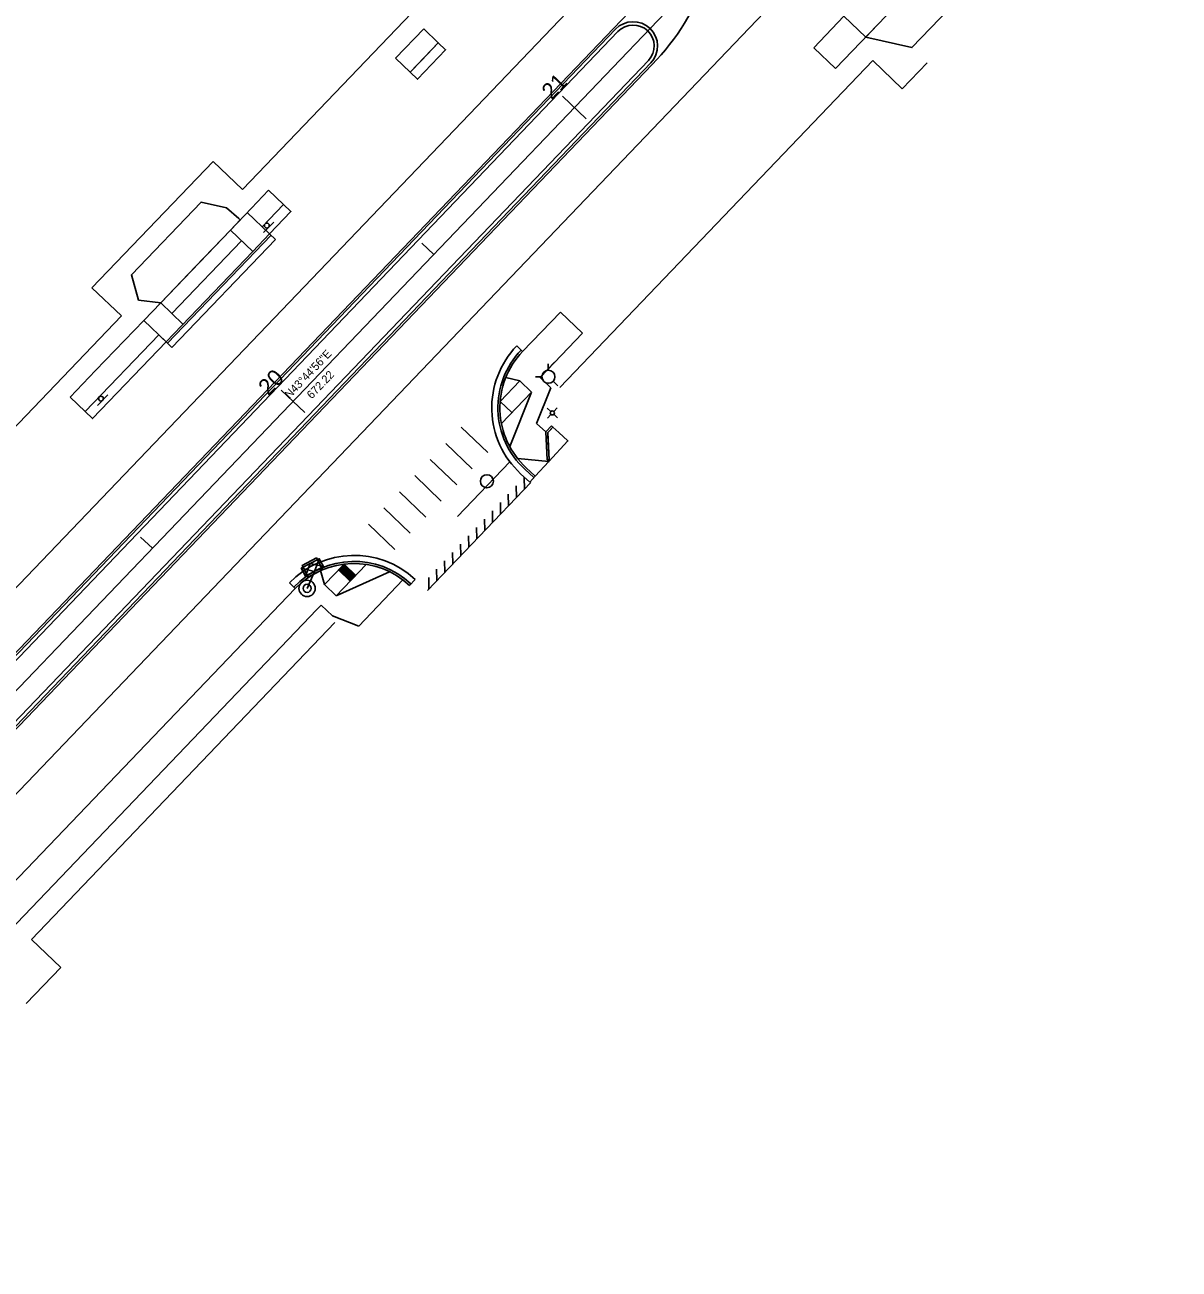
# Model space of a CAD drawing. Extents: x 2377903 to 2496516, y 664638 to 732785.
# Drawn here: x 2378536.6 to 2378820.2, y 730603.2 to 730909 of the extents above; entities that cross this region are included whole.
import ezdxf

# ---------------------------------------------------------------- set-up
doc = ezdxf.new("R2010")
doc.units = 0
for name, color, linetype in [('ALG_CL_BLUE_Horiz', 7, 'Continuous'), ('ALG_CL_BLUE_Horiz-Stationing', 7, 'Continuous'), ('ALG_CL_BLUE_Horiz-Text', 7, 'Continuous'), ('Default', 7, 'Continuous'), ('DES_ROADWAY_Approach', 7, 'Continuous'), ('DES_ROADWAY_Concrete-Pavement', 7, 'Continuous'), ('DES_ROADWAY_Curb-Back', 7, 'Continuous'), ('DES_ROADWAY_Curb-Face-LINE STYLE', 7, 'Continuous'), ('DES_ROADWAY_Edge-of-Pavement', 7, 'Continuous'), ('DES_ROADWAY_Misc-SAW CUT', 7, 'Continuous'), ('DES_ROADWAY_Sidewalk', 7, 'Continuous'), ('DES_ROADWAY_T-DOMES', 7, 'Continuous'), ('ENV_EROSN_Temp-Erosn-Ctrl-Details', 7, 'Continuous'), ('HYDR_Inlets', 7, 'Continuous'), ('ROW_P_PUA', 7, 'Continuous'), ('TOPO_WTRUTIL_Fire-Hydrant', 7, 'Continuous'), ('TOPO_WTRUTIL_Valve', 7, 'Continuous'), ('TRAF_PAVEMARK_Stop-Bar', 7, 'Continuous'), ('TRAF_PAVEMARK_White_SKIP 12-38', 7, 'Continuous'), ('TRAF_PAVEMARK_Yellow', 7, 'Continuous'), ('TRAF_SIGN_Post', 7, 'Continuous'), ('UTIL_STORM_Manhole', 7, 'Continuous'), ('UTIL_STORM_Pipe', 7, 'Continuous')]:
    doc.layers.add(name, color=color, linetype=linetype)

# ---------------------------------------------------------------- blocks, each defined once
blk = doc.blocks.new('MH_7')
at = {"layer": 'Default'}
for radius in [0.0254, 0.0127]:
    blk.add_circle((0, 0), radius, dxfattribs=at)
blk = doc.blocks.new('STSIGN_4')
at = {"layer": 'Default'}
for p, q in [((-0.0223, 0), (-0.0064, 0)), ((0, 0.0223), (0, 0.0064)), ((0.0064, 0), (0.0223, 0)), ((0, -0.0064), (0, -0.0223))]:
    blk.add_line(p, q, dxfattribs=at)
blk.add_circle((0, 0), 0.00635, dxfattribs=at)

msp = doc.modelspace()

# ---------------------------------------------------------------- linework, layer by layer
at = {"layer": 'ALG_CL_BLUE_Horiz'}
msp.add_line((2378375.43, 730579.33), (2378840.27, 731064.93), dxfattribs=at)
at = {"layer": 'ALG_CL_BLUE_Horiz-Stationing'}
for p, q in [((2378668.72, 730891.5), (2378674.5, 730885.97)), ((2378634.15, 730855.39), (2378637.04, 730852.62)), ((2378599.57, 730819.27), (2378605.35, 730813.73)), ((2378565, 730783.15), (2378567.89, 730780.38))]:
    msp.add_line(p, q, dxfattribs=at)
at = {"layer": 'Default'}
msp.add_line((2378572.68, 730838.08), (2378589.81, 730855.95), dxfattribs=at)
at = {"layer": 'DES_ROADWAY_Approach'}
for points in [[(2378762.97, 730926.67), (2378766.04, 730915.42), (2378754.57, 730903.46), (2378743.2, 730906.04), (2378746.11, 730909.08)], [(2378631.25, 730897.4), (2378638.16, 730904.63), (2378639.96, 730902.9), (2378633.05, 730895.67)], [(2378564.44, 730841.34), (2378562.74, 730847.59), (2378579.85, 730865.49), (2378586.11, 730864.08), (2378586.11, 730864.07), (2378589.12, 730861.46), (2378589.49, 730861.11), (2378587.08, 730858.58), (2378578.52, 730849.63), (2378569.96, 730840.68)], [(2378594.9, 730859.39), (2378600.14, 730864.88), (2378601.94, 730863.16), (2378596.7, 730857.66)], [(2378551.35, 730814), (2378569.44, 730832.87), (2378570.24, 730832.1), (2378571.24, 730831.14), (2378553.16, 730812.27)], [(2378665.38, 730802.12), (2378665.11, 730807.99), (2378665.1, 730808.29), (2378665.09, 730808.6), (2378665.08, 730808.82), (2378665.43, 730809.2), (2378665.49, 730809.27), (2378665.64, 730809.43), (2378666.31, 730810.17), (2378667.78, 730808.82), (2378670.02, 730806.78), (2378665.35, 730801.67)]]:
    msp.add_lwpolyline(points, close=True, dxfattribs=at)
at = {"layer": 'DES_ROADWAY_Concrete-Pavement'}
for p, q in [((2378524.37, 730742.39), (2378682.32, 730907.39)), ((2378689.78, 730900.25), (2378531.83, 730735.24))]:
    msp.add_line(p, q, dxfattribs=at)
msp.add_arc((2378686.05, 730903.82), 5.17, 316.2512, 136.2512, dxfattribs=at)
at = {"layer": 'DES_ROADWAY_Curb-Back'}
for p, q in [((2378524.37, 730742.39), (2378682.32, 730907.39)), ((2378531.83, 730735.24), (2378689.78, 730900.25)), ((2378661.99, 730798.11), (2378659.75, 730800.17))]:
    msp.add_line(p, q, dxfattribs=at)
msp.add_lwpolyline([(2378571.24, 730831.14), (2378592.54, 730853.33), (2378596.7, 730857.66)], dxfattribs=at)
for centre, radius, start, end in [((2378686.05, 730903.82), 5.17, 316.2512, 136.2512), ((2378673.3, 730814.89), 20, 136.1887, 227.3533), ((2378617.45, 730756.64), 20, 46.9312, 136.2336)]:
    msp.add_arc(centre, radius, start, end, dxfattribs=at)
at = {"layer": 'DES_ROADWAY_Curb-Face-LINE STYLE'}
for p, q in [((2378571.6, 730830.79), (2378597.06, 730857.31)), ((2378659.41, 730799.81), (2378661.65, 730797.75))]:
    msp.add_line(p, q, dxfattribs=at)
for centre, start, end in [((2378673.3, 730814.89), 136.1887, 227.3533), ((2378617.45, 730756.64), 46.9312, 136.2336)]:
    msp.add_arc(centre, 20.5, start, end, dxfattribs=at)
at = {"layer": 'DES_ROADWAY_Edge-of-Pavement'}
for p, q in [((2378523.76, 730742.96), (2378681.72, 730907.97)), ((2378532.43, 730734.67), (2378690.38, 730899.67)), ((2378596.7, 730857.66), (2378598.14, 730856.27)), ((2378572.68, 730829.76), (2378598.14, 730856.27)), ((2378571.24, 730831.14), (2378572.68, 730829.76)), ((2378658.87, 730828.73), (2378657.43, 730830.12)), ((2378658.4, 730798.7), (2378660.64, 730796.64)), ((2378635.5, 730770.03), (2378660.88, 730796.54)), ((2378661.99, 730798.11), (2378660.64, 730796.64)), ((2378601.56, 730771.86), (2378603, 730770.48)), ((2378631.1, 730771.25), (2378632.47, 730772.71))]:
    msp.add_line(p, q, dxfattribs=at)
for centre, radius, start, end in [((2378686.05, 730903.82), 6, 316.2512, 136.2512), ((2378673.3, 730814.89), 22, 136.1887, 227.3533), ((2378617.45, 730756.64), 22, 46.9312, 136.2336)]:
    msp.add_arc(centre, radius, start, end, dxfattribs=at)
at = {"layer": 'DES_ROADWAY_Misc-SAW CUT'}
for p, q in [((2378657.39, 730792.89), (2378657.33, 730795.72)), ((2378659.34, 730794.94), (2378659.28, 730797.77)), ((2378655.43, 730790.85), (2378655.37, 730793.68)), ((2378651.51, 730786.76), (2378651.45, 730789.59)), ((2378653.47, 730788.8), (2378653.41, 730791.63)), ((2378649.56, 730784.71), (2378649.5, 730787.54)), ((2378645.64, 730780.62), (2378645.58, 730783.45)), ((2378647.6, 730782.67), (2378647.54, 730785.5)), ((2378643.68, 730778.58), (2378643.62, 730781.41)), ((2378639.77, 730774.49), (2378639.71, 730777.32)), ((2378641.73, 730776.53), (2378641.67, 730779.36)), ((2378637.81, 730772.44), (2378637.75, 730775.27)), ((2378635.85, 730770.4), (2378635.8, 730773.23))]:
    msp.add_line(p, q, dxfattribs=at)
at = {"layer": 'DES_ROADWAY_Sidewalk'}
for p, q in [((2378737.85, 730911.18), (2378730.44, 730903.42)), ((2378735.79, 730898.31), (2378746.11, 730909.08)), ((2378743.2, 730906.04), (2378737.85, 730911.18)), ((2378634.6, 730908.03), (2378627.66, 730900.83)), ((2378638.16, 730904.63), (2378634.6, 730908.03)), ((2378634, 730900.28), (2378638.16, 730904.63)), ((2378735.79, 730898.31), (2378730.44, 730903.42)), ((2378631.25, 730897.4), (2378627.66, 730900.83)), ((2378631.25, 730897.4), (2378634, 730900.28)), ((2378596.45, 730868.41), (2378592.25, 730864)), ((2378600.14, 730864.88), (2378596.45, 730868.41)), ((2378592.25, 730864), (2378587.08, 730858.58)), ((2378591.22, 730862.92), (2378596.7, 730857.66)), ((2378594.9, 730859.39), (2378600.14, 730864.88)), ((2378587.08, 730858.58), (2378569.96, 730840.68)), ((2378587.08, 730858.58), (2378592.54, 730853.33)), ((2378569.96, 730840.68), (2378565.79, 730836.37)), ((2378569.96, 730840.68), (2378575.39, 730835.47)), ((2378668.18, 730838.44), (2378658.87, 730828.73)), ((2378673.58, 730833.26), (2378668.18, 730838.44)), ((2378553.89, 730824.05), (2378565.79, 730836.37)), ((2378565.79, 730836.37), (2378571.24, 730831.14)), ((2378569.44, 730832.87), (2378551.35, 730814)), ((2378663.16, 730822.34), (2378673.58, 730833.26)), ((2378663.3, 730822.49), (2378666.75, 730826.11)), ((2378547.65, 730817.55), (2378553.89, 730824.05)), ((2378653.37, 730816.49), (2378658.21, 730821.54)), ((2378654.74, 730822.33), (2378658.21, 730821.54)), ((2378661.1, 730818.78), (2378658.21, 730821.54)), ((2378665.82, 730819.79), (2378662.31, 730811.09)), ((2378665.82, 730819.79), (2378663.16, 730822.34)), ((2378551.35, 730814), (2378547.65, 730817.55)), ((2378653.68, 730811.04), (2378661.1, 730818.78)), ((2378661.1, 730818.78), (2378655.7, 730805.39)), ((2378656.25, 730813.72), (2378653.37, 730816.49)), ((2378662.31, 730811.09), (2378664.57, 730809.01)), ((2378664.57, 730809.01), (2378665.94, 730810.51)), ((2378664.88, 730802.1), (2378664.57, 730809.01)), ((2378665.08, 730808.82), (2378666.31, 730810.17)), ((2378665.38, 730802.12), (2378665.08, 730808.82)), ((2378666.31, 730810.17), (2378665.94, 730810.51)), ((2378657.67, 730802.41), (2378665.35, 730801.67)), ((2378665.35, 730801.67), (2378661.99, 730798.11)), ((2378664.88, 730802.1), (2378665.38, 730802.12)), ((2378664.88, 730802.1), (2378665.35, 730801.67)), ((2378610.16, 730771.44), (2378609.23, 730774.88)), ((2378610.16, 730771.44), (2378615.01, 730776.49)), ((2378613.05, 730768.67), (2378620.47, 730776.41)), ((2378613.05, 730768.67), (2378626.2, 730774.62)), ((2378617.89, 730773.72), (2378615.01, 730776.49)), ((2378613.05, 730768.67), (2378610.16, 730771.44)), ((2378629.43, 730772.65), (2378618.64, 730761.23)), ((2378527.48, 730691.63), (2378603, 730770.48)), ((2378609.4, 730766.39), (2378608.17, 730765.16)), ((2378612.12, 730763.79), (2378609.4, 730766.39)), ((2378612.12, 730763.79), (2378618.64, 730761.23))]:
    msp.add_line(p, q, dxfattribs=at)
msp.add_lwpolyline([(2378532.77, 730686.32), (2378606.65, 730763.63), (2378608.17, 730765.16)], dxfattribs=at)
at = {"layer": 'DES_ROADWAY_T-DOMES'}
for p, q in [((2378613.62, 730775.05), (2378616.51, 730772.28)), ((2378615.01, 730776.49), (2378617.89, 730773.72))]:
    msp.add_line(p, q, dxfattribs=at)
msp.add_lwpolyline([(2378616.51, 730772.28), (2378613.62, 730775.05), (2378615.01, 730776.49), (2378617.89, 730773.72)], close=True, dxfattribs=at)
for centre in [(2378613.92, 730775.07), (2378614.05, 730775.21), (2378614.06, 730774.93), (2378614.19, 730775.35), (2378614.2, 730775.07), (2378614.2, 730774.79), (2378614.33, 730775.5), (2378614.34, 730775.22), (2378614.34, 730774.93), (2378614.35, 730774.65), (2378614.47, 730775.64), (2378614.48, 730775.36), (2378614.48, 730775.08), (2378614.49, 730774.79), (2378614.49, 730774.51), (2378614.61, 730775.79), (2378614.61, 730775.5), (2378614.62, 730775.22), (2378614.63, 730774.94), (2378614.63, 730774.66), (2378614.64, 730774.37), (2378614.75, 730775.93), (2378614.75, 730775.65), (2378614.76, 730775.37), (2378614.76, 730775.08), (2378614.77, 730774.8), (2378614.78, 730774.52), (2378614.78, 730774.23), (2378614.89, 730776.08), (2378614.89, 730775.79), (2378614.9, 730775.51), (2378614.9, 730775.23), (2378614.91, 730774.94), (2378614.91, 730774.66), (2378614.92, 730774.38), (2378614.93, 730774.1), (2378615.02, 730776.22), (2378615.03, 730775.94), (2378615.04, 730775.65), (2378615.04, 730775.37), (2378615.05, 730775.09), (2378615.05, 730774.81), (2378615.06, 730774.52), (2378615.06, 730774.24), (2378615.07, 730773.96), (2378615.17, 730776.08), (2378615.17, 730775.8), (2378615.18, 730775.52), (2378615.19, 730775.23), (2378615.19, 730774.95), (2378615.2, 730774.67), (2378615.2, 730774.38), (2378615.21, 730774.1), (2378615.31, 730775.94), (2378615.32, 730775.66), (2378615.32, 730775.38), (2378615.33, 730775.09), (2378615.34, 730774.81), (2378615.34, 730774.53), (2378615.35, 730774.25), (2378615.35, 730773.96), (2378615.46, 730775.8), (2378615.46, 730775.52), (2378615.47, 730775.24), (2378615.47, 730774.96), (2378615.48, 730774.67), (2378615.49, 730774.39), (2378615.49, 730774.11), (2378615.6, 730775.67), (2378615.61, 730775.38), (2378615.61, 730775.1), (2378615.62, 730774.82), (2378615.62, 730774.53), (2378615.63, 730774.25), (2378615.64, 730773.97), (2378615.75, 730775.53), (2378615.75, 730775.24), (2378615.76, 730774.96), (2378615.76, 730774.68), (2378615.77, 730774.4), (2378615.77, 730774.11), (2378615.89, 730775.39), (2378615.9, 730775.11), (2378615.9, 730774.82), (2378615.91, 730774.54), (2378615.91, 730774.26), (2378615.92, 730773.97), (2378616.03, 730775.25), (2378616.04, 730774.97), (2378616.05, 730774.68), (2378616.05, 730774.4), (2378616.06, 730774.12), (2378616.06, 730773.84), (2378616.18, 730775.11), (2378616.18, 730774.83), (2378616.19, 730774.55), (2378616.2, 730774.26), (2378616.2, 730773.98), (2378616.32, 730774.97), (2378616.33, 730774.69), (2378616.33, 730774.41), (2378616.34, 730774.12), (2378616.35, 730773.84), (2378616.47, 730774.83), (2378616.47, 730774.55), (2378616.48, 730774.27), (2378616.48, 730773.99), (2378616.61, 730774.7), (2378616.62, 730774.41), (2378616.62, 730774.13), (2378616.63, 730773.85), (2378616.76, 730774.56), (2378616.76, 730774.27), (2378616.77, 730773.99), (2378616.9, 730774.42), (2378616.91, 730774.14), (2378616.91, 730773.85), (2378617.04, 730774.28), (2378617.05, 730774), (2378617.19, 730774.14), (2378617.19, 730773.86), (2378617.33, 730774), (2378617.48, 730773.86), (2378615.21, 730773.82), (2378615.36, 730773.68), (2378615.5, 730773.82), (2378615.5, 730773.54), (2378615.64, 730773.69), (2378615.65, 730773.4), (2378615.78, 730773.83), (2378615.79, 730773.55), (2378615.79, 730773.26), (2378615.92, 730773.69), (2378615.93, 730773.41), (2378615.94, 730773.13), (2378616.07, 730773.55), (2378616.07, 730773.27), (2378616.08, 730772.99), (2378616.21, 730773.7), (2378616.21, 730773.41), (2378616.22, 730773.13), (2378616.22, 730772.85), (2378616.35, 730773.56), (2378616.36, 730773.28), (2378616.36, 730772.99), (2378616.37, 730772.71), (2378616.49, 730773.7), (2378616.5, 730773.42), (2378616.5, 730773.14), (2378616.51, 730772.85), (2378616.51, 730772.57), (2378616.63, 730773.56), (2378616.64, 730773.28), (2378616.65, 730773), (2378616.65, 730772.72), (2378616.77, 730773.71), (2378616.78, 730773.43), (2378616.78, 730773.14), (2378616.79, 730772.86), (2378616.92, 730773.57), (2378616.92, 730773.29), (2378616.93, 730773), (2378617.06, 730773.71), (2378617.06, 730773.43), (2378617.07, 730773.15), (2378617.2, 730773.58), (2378617.21, 730773.29), (2378617.34, 730773.72), (2378617.34, 730773.44), (2378617.48, 730773.58), (2378617.62, 730773.73)]:
    msp.add_circle(centre, 0.0375, dxfattribs=at)
at = {"layer": 'ENV_EROSN_Temp-Erosn-Ctrl-Details'}
msp.add_lwpolyline([(2378609.93, 730775.87), (2378605.52, 730773.51), (2378604.48, 730775.45), (2378608.89, 730777.81)], close=True, dxfattribs=at)
for points in [[(2378608.89, 730777.81), (2378607.72, 730774.69), (2378604.48, 730775.45)], [(2378605.52, 730773.51), (2378606.68, 730776.63), (2378609.93, 730775.87)]]:
    msp.add_lwpolyline(points, dxfattribs=at)
at = {"layer": 'HYDR_Inlets'}
msp.add_lwpolyline([(2378606.19, 730773.31), (2378609.72, 730775.19), (2378608.22, 730778.01), (2378604.69, 730776.13)], close=True, dxfattribs=at)
at = {"layer": 'ROW_P_PUA'}
for p, q in [((2378590.01, 730868.57), (2378681.63, 730964.28)), ((2378668.04, 730819.93), (2378744.92, 730900.24)), ((2378752.14, 730893.33), (2378744.92, 730900.24)), ((2378752.14, 730893.33), (2378758.28, 730899.74)), ((2378553.05, 730844.42), (2378582.79, 730875.48)), ((2378582.79, 730875.48), (2378590.01, 730868.57)), ((2378553.05, 730844.42), (2378560.28, 730837.5)), ((2378479.37, 730752.99), (2378560.28, 730837.5)), ((2378538.16, 730684.25), (2378612.72, 730762.14)), ((2378545.38, 730677.33), (2378538.16, 730684.25)), ((2378536.91, 730668.48), (2378545.38, 730677.33))]:
    msp.add_line(p, q, dxfattribs=at)
at = {"layer": 'TOPO_WTRUTIL_Fire-Hydrant'}
for p, q in [((2378665.2, 730824.13), (2378665.17, 730825.71)), ((2378663.64, 730822.52), (2378662.05, 730822.5)), ((2378666.37, 730821.43), (2378667.52, 730820.32))]:
    msp.add_line(p, q, dxfattribs=at)
msp.add_circle((2378665.22, 730822.54), 1.6, dxfattribs=at)
at = {"layer": 'TOPO_WTRUTIL_Valve'}
msp.add_circle((2378650.11, 730796.86), 1.6, dxfattribs=at)
at = {"layer": 'TRAF_PAVEMARK_Stop-Bar'}
for p, q in [((2378643.81, 730810.14), (2378650.31, 730803.91)), ((2378640.01, 730806.17), (2378646.5, 730799.94)), ((2378636.2, 730802.2), (2378642.7, 730795.97)), ((2378642.86, 730788.2), (2378655.74, 730801.63)), ((2378632.39, 730798.23), (2378638.89, 730792)), ((2378628.59, 730794.26), (2378635.08, 730788.03)), ((2378624.78, 730790.29), (2378631.28, 730784.07)), ((2378620.97, 730786.32), (2378627.47, 730780.1))]:
    msp.add_line(p, q, dxfattribs=at)
at = {"layer": 'TRAF_PAVEMARK_White_SKIP 12-38'}
for p, q in [((2378398.38, 730628.61), (2378793.36, 731041.22)), ((2378421.23, 730601.86), (2378814.84, 731013.05))]:
    msp.add_line(p, q, dxfattribs=at)
at = {"layer": 'TRAF_PAVEMARK_Yellow'}
for p, q in [((2378523.4, 730743.31), (2378785.05, 731016.64)), ((2378429.1, 730625.99), (2378690.75, 730899.32))]:
    msp.add_line(p, q, dxfattribs=at)
msp.add_arc((2378651.91, 730937.94), 54.76, 315.1621, 342.1744, dxfattribs=at)
at = {"layer": 'TRAF_SIGN_Post'}
for p, q in [((2378597.7, 730860.58), (2378595.21, 730857.98)), ((2378556.93, 730818.06), (2378554.44, 730815.46))]:
    msp.add_line(p, q, dxfattribs=at)
for centre in [(2378596.02, 730859.7), (2378555.25, 730817.17)]:
    msp.add_circle(centre, 0.6, dxfattribs=at)
at = {"layer": 'UTIL_STORM_Pipe'}
msp.add_line((2378605.92, 730770.52), (2378607.72, 730774.69), dxfattribs=at)

# ---------------------------------------------------------------- block references
at = {"layer": 'TRAF_SIGN_Post', "xscale": 78.74000000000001, "yscale": 78.74000000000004, "rotation": -42.76333832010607}
msp.add_blockref('STSIGN_4', (2378666.18, 730813.65), dxfattribs=at)
at = {"layer": 'UTIL_STORM_Manhole', "xscale": 78.74000000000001, "yscale": 78.74000000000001}
msp.add_blockref('MH_7', (2378605.92, 730770.52), dxfattribs=at)

# ---------------------------------------------------------------- texts
at = {"layer": 'ALG_CL_BLUE_Horiz-Stationing'}
for s, p in [('21', (2378666.04, 730890.43)), ('20', (2378596.41, 730817.7))]:
    msp.add_text(s, height=4, rotation=46.2512, dxfattribs=at).set_placement(p)
at = {"layer": 'ALG_CL_BLUE_Horiz-Text'}
for s, p in [('N43°44\'56"E', (2378601.61, 730817.05)), ('672.22', (2378607.06, 730816.96))]:
    msp.add_text(s, height=2, rotation=46.2512, dxfattribs=at).set_placement(p)

doc.saveas('drawing.dxf')
